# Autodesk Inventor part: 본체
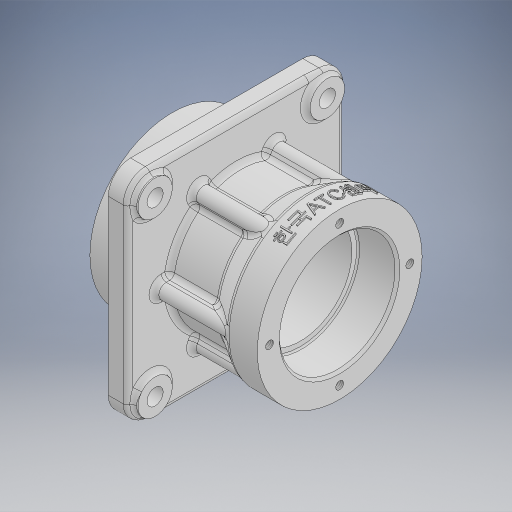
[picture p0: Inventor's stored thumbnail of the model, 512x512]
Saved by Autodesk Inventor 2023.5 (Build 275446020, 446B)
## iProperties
Created: 2025-08
Part Number: 본체
Material: 일반
Document SubType Name: Modeling
Designer: 1강의실14
Density: 1 g/cm^3
Appearance: 기본값
Author: 1강의실14
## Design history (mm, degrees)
sketch "스케치1"
  geometry: C1 r 27.5 at (0, 0); 1 further point
  constraints: 1 centre point, 1 coincident
  dimensions: "d0" = 55 diameter of C1
extrude "돌출1" new body sketch "스케치1" stored distance "d1" = 68; taper "d2" = 0 deg
sketch "스케치2"
  geometry: C1 r 33.5 at (0, 0); 1 further point
  constraints: 1 centre point, 1 coincident
  dimensions: "d3" = 67 diameter of C1
extrude "돌출2" join sketch "스케치2" distance "d4" = 13; taper "d5" = 0 deg
sketch "스케치3"
  geometry: C1 r 38.5 at (0, 0); 1 further point
  constraints: 1 centre point, 1 coincident
  dimensions: "d6" = 77 diameter of C1
extrude "돌출3" join sketch "스케치3" distance "d7" = 5; taper "d8" = 0 deg
sketch "스케치4"
  geometry: L1 (-35, -44)-(35, -44); L2 (44, -35)-(44, 35); L3 (35, 44)-(-35, 44); L4 (-44, 35)-(-44, -35); L5 (-44, -44)-(44, 44); L6 (44, -44)-(-44, 44); A1 r 9 centre (-35, 35) between (-35, 44) and (-44, 35); A2 r 9 centre (-35, -35) between (-44, -35) and (-35, -44); A3 r 9 centre (35, -35) between (35, -44) and (44, -35); A4 r 9 centre (35, 35) between (44, 35) and (35, 44); 1 further point
  constraints: 12 end point, 8 point on circle, 8 point on line, 8 tangent, 4 centre point, 3 equal radius, 2 midpoint, 2 parallel, 1 horizontal, 1 perpendicular
  dimensions: "d9" = 88 distance of L6.start L5.end; "d10" = 88 distance of L5.end L6.end; "d11" = 9 radius of A1
extrude "돌출4" join sketch "스케치4" distance "d12" = 8; taper "d13" = 0 deg
sketch "스케치5"
  geometry: C1 r 33.5 at (0, 0); 1 further point
  constraints: 1 centre point, 1 coincident
  dimensions: "d14" = 67 diameter of C1
extrude "돌출5" join sketch "스케치5" distance "d15" = 12; taper "d16" = 0 deg
sketch "스케치6"
  geometry: L1 (34, 33.5)-(22, 33.5) reference; L2 (22, 33.5)-(12, 27.5); L3 (-8, 27.5)-(22, 27.5) reference; L4 (12, 27.5)-(12, 0); L5 (22, 33.5)-(22, 0); L6 (22, 33.5)-(22, -33.5) reference; L7 (12, 0)-(22, 0); 3 further points
  constraints: 8 end point, 2 midpoint, 2 point on line, 1 horizontal alignment, 1 perpendicular, 1 vertical
  dimensions: "d17" = 10 distance between parallel lines of L5 L4
revolve "회전1" sketch "스케치6" stored, may be unused: angle "d18" = 90 deg
sketch "스케치7"
  geometry: L1 (-34, 33.5)-(-34, -33.5) reference; L2 (-34, 0)-(34, 0); L3 (34, -33.5)-(34, 33.5) reference; L4 (34, 0)-(34, 23.5); L5 (34, 23.5)-(18.6, 23.5); L6 (18, 22.9)-(18, 21); L7 (18, 21)-(-18, 21); L8 (-18, 21)-(-18, 22.9); L9 (-18.6, 23.5)-(-34, 23.5); L10 (-34, 23.5)-(-34, 0); A1 r 0.6 centre (18.6, 22.9) between (18.6, 23.5) and (18, 22.9); A2 r 0.6 centre (-18.6, 22.9) between (-18, 22.9) and (-18.6, 23.5); 3 further points
  constraints: 16 end point, 6 point on line, 4 perpendicular, 4 point on circle, 4 tangent, 2 centre point, 2 midpoint, 1 collinear, 1 equal radius, 1 vertical
  dimensions: "d19" = 47 diameter of L5 L2; "d20" = 16 distance of L4.end point (18, 23.5); "d21" = 16 distance of point (-18, 23.5) L9.end; "d22" = 42 diameter of L7 L2; "d76" = 0.6 radius of A1
revolve "회전2" sketch "스케치7" stored, may be unused: angle "d23" = 90 deg
sketch "스케치8"
  geometry: L1 (44, -35)-(44, 35) reference; L2 (35, 44)-(-35, 44) reference; L3 (-44, 35)-(-44, -35) reference; L4 (-35, -44)-(35, -44) reference; C1 r 27.5 at (0, 0) reference; C2 r 7 at (-35, 35); C3 r 3.3 at (-35, 35); C4 r 7 at (35, 35); C5 r 3.3 at (35, 35); C6 r 7 at (-35, -35); C7 r 3.3 at (-35, -35); C8 r 7 at (35, -35); C9 r 3.3 at (35, -35); A1 r 9 centre (35, -35) between (35, -44) and (44, -35) reference; A2 r 9 centre (35, 35) between (44, 35) and (35, 44) reference; A3 r 9 centre (-35, 35) between (-35, 44) and (-44, 35) reference; A4 r 9 centre (-35, -35) between (-44, -35) and (-35, -44) reference; 1 further point
  constraints: 8 centre point, 8 coincident
  dimensions: "d24" = 14 diameter of C2; "d25" = 6.6 diameter of C3; "d26" = 14 diameter of C4; "d27" = 6.6 diameter of C5; "d28" = 14 diameter of C6; "d29" = 6.6 diameter of C7; "d30" = 14 diameter of C8; "d31" = 6.6 diameter of C9
  node "투영된 루프1"
extrude "돌출6" join sketch "스케치8" distance "d32" = 2; taper "d33" = 0 deg
extrude "돌출7" cut sketch "스케치8" stored distance "d34" = 2; taper "d35" = 0 deg
sketch "스케치9"
  geometry: L1 (-15.25, 26.414)-(0, 0); L2 (-17.848, 24.914)-(-2.598, -1.5); L3 (2.598, 1.5)-(-12.652, 27.914); L4 (0, 0)-(0, 44); L5 (35, 44)-(-35, 44) reference; C1 r 23.5 at (0, 0) reference; C2 r 33.5 at (0, 0) reference; C3 r 23.5 at (0, 0) reference; C4 r 23.5 at (0, 0) reference; C5 r 23.5 at (0, 0); A1 r 3 centre (-15.25, 26.414) between (-12.652, 27.914) and (-17.848, 24.914); A2 r 3 centre (0, 0) between (-2.598, -1.5) and (2.598, 1.5); 4 further points
  constraints: 10 end point, 5 tangent, 4 point on circle, 3 centre point, 2 coincident, 2 midpoint, 1 concentric, 1 parallel
  dimensions: "d36" = 6 distance between parallel lines of L2 L3; "d37" = 30 deg angle of L4 L1
extrude "돌출8" join sketch "스케치9" stored distance "d38" = 10; taper "d39" = 0 deg
sketch "스케치10"
  geometry: L1 (-34, 33.5)-(-34, -33.5) reference; 3 further points
  constraints: 1 horizontal alignment, 1 midpoint, 1 other
  dimensions: "d43" = 6 distance from line of point (-28, 0) L1
feature "엠보싱1" sketch "스케치10" dims "d9" = 88, "d10" = 88, "d11" = 9, "d44" = 0.5, "d45" = 0
fillet "모깎기2" dims "d47" = 2
chamfer "모따기1" distance "d48" = 1; stored, may be unused: second distance "d49" = 2, angle "d50" = 45 deg
sketch "스케치11" dims "d58" = 57
  geometry: 3 further points
  constraints: 2 vertical alignment, 1 coincident, 2 other
hole "구멍1" sketch "스케치11" at (0, 28.5) diameter "d51" = 3.242; stored, may be unused: countersink angle "d55" = 90 deg, drill point angle "d57" = 118 deg; dims "d52" = 8, "d53" = 15, "d54" = 4, "d56" = 10
sketch "스케치12" dims "d69" = 57
  geometry: 3 further points
  constraints: 2 vertical alignment, 1 coincident, 2 other
hole "구멍2" sketch "스케치12" at (0, 28.5) diameter "d62" = 3.242; stored, may be unused: countersink angle "d66" = 90 deg, drill point angle "d68" = 118 deg; dims "d63" = 8, "d64" = 4, "d65" = 2, "d67" = 10
fillet "모깎기3" dims "d73" = 2
fillet "모깎기6" dims "d77" = 2
fillet "모깎기7" dims "d78" = 2
chamfer "모따기2" distance "d79" = 1; stored, may be unused: second distance "d80" = 2, angle "d81" = 45 deg
feature "й耀л耀н耀п耀с耀у耀х耀ч耀" dims "d0" = 55, "d1" = 68, "d2" = 0, "d3" = 67, "d4" = 13, "d5" = 0, "d6" = 77, "d7" = 5, "d8" = 0, "d9" = 88, "d10" = 88, "d11" = 9, "d12" = 8, "d13" = 0, "d14" = 67, "d15" = 12, "d16" = 0, "d17" = 10, "d18" = 90 deg, "d19" = 47, "d20" = 16, "d21" = 16, "d22" = 42, "d23" = 90 deg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
node "솔리드1"
pattern_circular "원형 패턴1" dims angle "d41" = 360 deg
pattern_circular "원형 패턴2" dims angle "d60" = 360 deg
pattern_circular "원형 패턴3" dims angle "d71" = 360 deg
node "투영된 루프2"
feature "A9D066F2-1C7D-4E18-AEED-F7BC21143FA4" dims "d51" = 3.242, "d52" = 8, "d53" = 15, "d54" = 4, "d55" = 90 deg, "d56" = 10, "d57" = 118 deg
